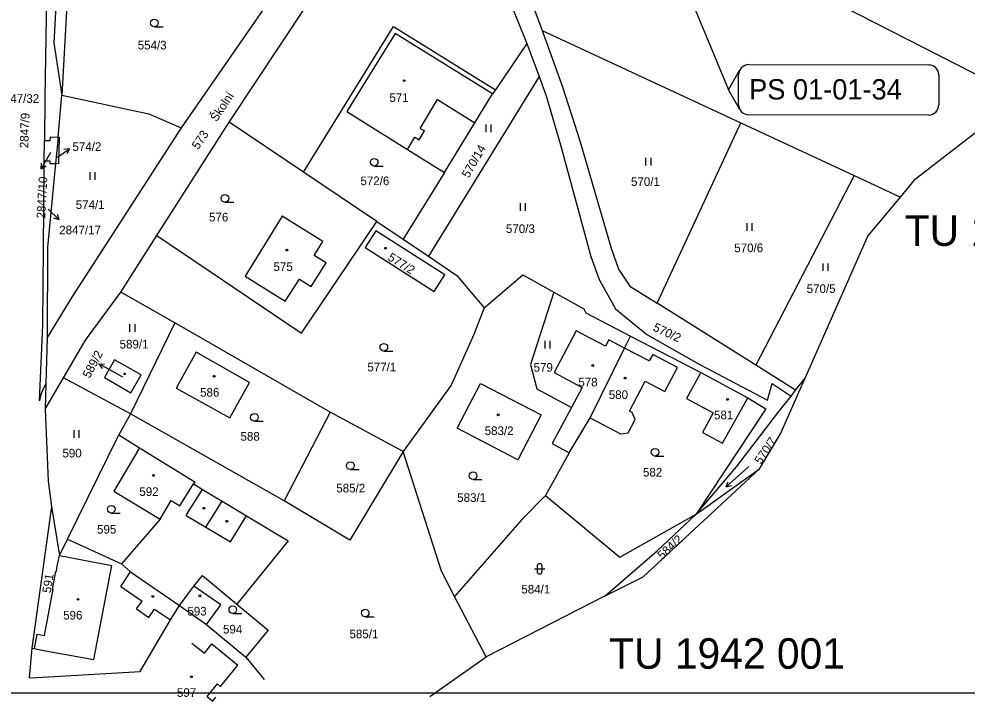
# Model space of a CAD drawing. Extents: x -558358 to -557517, y -1073786 to -1073189.
# Drawn here: x -558184.5 to -557998, y -1073785.7 to -1073651.5 of the extents above; entities that cross this region are included whole.
import ezdxf

# ---------------------------------------------------------------- set-up
doc = ezdxf.new("R2010")
doc.units = 0
for name, color, linetype in [('Hranice parcel', 7, 'Continuous'), ('Parcelní čísla', 7, 'Continuous'), ('Pop  PČ popisy', 7, 'Continuous'), ('Vnitřní kresba', 7, 'Continuous'), ('Vrstva 1', 7, 'Continuous'), ('Vrstva 2', 7, 'Continuous'), ('Vrstva 28', 7, 'Continuous'), ('Značky budov', 7, 'Continuous'), ('Značky kultur', 7, 'Continuous')]:
    doc.layers.add(name, color=color, linetype=linetype)

msp = doc.modelspace()

# ---------------------------------------------------------------- linework, layer by layer
at = {"layer": 'Hranice parcel'}
for p, q in [((-558126.57, -1073635.37), (-558152.59, -1073672.96)), ((-558047.53, -1073636.2), (-557987.38, -1073666.93)), ((-558083.83, -1073647.78), (-558081.75, -1073653.27)), ((-558081.75, -1073653.27), (-558081.56, -1073653.8)), ((-558081.56, -1073653.8), (-558042.48, -1073671.96)), ((-558084.61, -1073656.37), (-558090.78, -1073665.45)), ((-558084.61, -1073656.37), (-558082.19, -1073662.86)), ((-558082.19, -1073662.86), (-558103.95, -1073698.19)), ((-558082.19, -1073662.86), (-558080.79, -1073666.61)), ((-558090.78, -1073665.45), (-558091.34, -1073666.27)), ((-558176.83, -1073674.75), (-558176.05, -1073666.5)), ((-558008.13, -1073682.96), (-557987.38, -1073666.93)), ((-558157.39, -1073694.14), (-558143.16, -1073671.79)), ((-558128.54, -1073681.64), (-558143.16, -1073671.79)), ((-558058.98, -1073707.44), (-558042.48, -1073671.96)), ((-558042.48, -1073671.96), (-558020.18, -1073682.32)), ((-558178.3, -1073674.68), (-558176.83, -1073674.75)), ((-558176.83, -1073674.75), (-558177.33, -1073679.98)), ((-558176.83, -1073674.75), (-558176.6, -1073674.76)), ((-558176.6, -1073674.76), (-558176.71, -1073680)), ((-558179.54, -1073679.43), (-558179.49, -1073675.4)), ((-558178.45, -1073679.93), (-558177.33, -1073679.98)), ((-558176.71, -1073680), (-558177.33, -1073679.98)), ((-558114.13, -1073691.34), (-558128.54, -1073681.64)), ((-558100.81, -1073681.69), (-558108.93, -1073694.83)), ((-558020.18, -1073682.32), (-558039.55, -1073719.63)), ((-558020.18, -1073682.32), (-558011.11, -1073686.54)), ((-558011.11, -1073686.54), (-558008.13, -1073682.96)), ((-558017.53, -1073694.23), (-558011.11, -1073686.54)), ((-558114.13, -1073691.34), (-558108.93, -1073694.83)), ((-558164.46, -1073705.23), (-558157.39, -1073694.14)), ((-558108.93, -1073694.83), (-558103.95, -1073698.19)), ((-558029.85, -1073722.15), (-558017.53, -1073694.23)), ((-558153.86, -1073711.3), (-558164.46, -1073705.23)), ((-558079.26, -1073705.23), (-558083.89, -1073719.49)), ((-558039.55, -1073719.63), (-558058.98, -1073707.44)), ((-558153.86, -1073711.3), (-558162.58, -1073729.18)), ((-558123.29, -1073728.86), (-558153.86, -1073711.3)), ((-558178.98, -1073714.16), (-558179.23, -1073723.31)), ((-558065.38, -1073716.24), (-558064.19, -1073713.89)), ((-558064.19, -1073713.89), (-558050.38, -1073721.04)), ((-558072.16, -1073729.98), (-558065.38, -1073716.24)), ((-558083.89, -1073719.49), (-558082.62, -1073724.25)), ((-558031.72, -1073724.54), (-558039.55, -1073719.63)), ((-558050.38, -1073721.04), (-558041.12, -1073726.03)), ((-558179.37, -1073728.25), (-558175.74, -1073722.09)), ((-558179.23, -1073723.31), (-558179.37, -1073728.25)), ((-558162.58, -1073729.18), (-558175.74, -1073722.09)), ((-558031.72, -1073724.54), (-558029.85, -1073722.15)), ((-558082.62, -1073724.25), (-558075.83, -1073727.93)), ((-558032.62, -1073725.69), (-558031.72, -1073724.54)), ((-558162.58, -1073729.18), (-558164.87, -1073733.32)), ((-558132.34, -1073746.32), (-558162.58, -1073729.18)), ((-558123.29, -1073728.86), (-558132.34, -1073746.32)), ((-558108.92, -1073736.57), (-558123.29, -1073728.86)), ((-558076.28, -1073736.83), (-558072.16, -1073729.98)), ((-558174.95, -1073753.84), (-558164.87, -1073733.32)), ((-558164.87, -1073733.32), (-558160.79, -1073735.84)), ((-558076.28, -1073736.83), (-558080.95, -1073745.27)), ((-558061.7, -1073761.21), (-558038.85, -1073740)), ((-558051.32, -1073748.93), (-558043.37, -1073739.61)), ((-558051.32, -1073748.93), (-558038.85, -1073740)), ((-558080.95, -1073745.27), (-558085.52, -1073749.88)), ((-558178.08, -1073747.39), (-558181.97, -1073775.25)), ((-558178.08, -1073747.39), (-558176.52, -1073757.07)), ((-558058.99, -1073756.15), (-558051.32, -1073748.93)), ((-558085.52, -1073749.88), (-558098.82, -1073765.08)), ((-558176.52, -1073757.07), (-558174.95, -1073753.84)), ((-558174.95, -1073753.84), (-558164.36, -1073758.7)), ((-558069.16, -1073765.01), (-558058.99, -1073756.15)), ((-558069.16, -1073765.01), (-558061.7, -1073761.21)), ((-558152.96, -1073766.88), (-558150.14, -1073763.05)), ((-558092.62, -1073776.97), (-558098.82, -1073765.08)), ((-558069.16, -1073765.01), (-558092.62, -1073776.97)), ((-558152.96, -1073766.88), (-558147.64, -1073770.59)), ((-558147.64, -1073770.59), (-558147.54, -1073770.67)), ((-558147.54, -1073770.67), (-558139.85, -1073777.06)), ((-558181.97, -1073775.25), (-558182.51, -1073781.13)), ((-558139.85, -1073777.06), (-558136.25, -1073781.43)), ((-558103.7, -1073784.79), (-558092.62, -1073776.97)), ((-558182.51, -1073781.13), (-558181.01, -1073781.05))]:
    msp.add_line(p, q, dxfattribs=at)
for points in [[(-558086.19, -1073392.25), (-558100.56, -1073410.01), (-558117.51, -1073431.08), (-558131.78, -1073449.27), (-558138.48, -1073457.68), (-558143.38, -1073464.02), (-558146.99, -1073468.89), (-558150.46, -1073473.83), (-558152.02, -1073476.41), (-558154.26, -1073480.97), (-558156.46, -1073486.6), (-558158.91, -1073494.31), (-558160.3, -1073500.48), (-558162.16, -1073510.4), (-558165.76, -1073536.46), (-558169.94, -1073565.43), (-558173.74, -1073591.61), (-558177.66, -1073620.33), (-558178.51, -1073631.87), (-558179.02, -1073643), (-558179.24, -1073655.12), (-558179.45, -1073666.94), (-558179.49, -1073675.4)], [(-558175.82, -1073622.18), (-558177.63, -1073656.22), (-558176.05, -1073666.5)], [(-558175.82, -1073622.18), (-558174.18, -1073632.38), (-558176.05, -1073666.5)], [(-558143.16, -1073671.79), (-558122.68, -1073640.91), (-558116.74, -1073631.82), (-558110.18, -1073623.69)], [(-558110.18, -1073623.69), (-558095.16, -1073631.27), (-558088.2, -1073647.35), (-558084.61, -1073656.37)], [(-558128.54, -1073681.64), (-558110.84, -1073652.98), (-558090.78, -1073665.45)], [(-558091.34, -1073666.27), (-558110.52, -1073654.36), (-558120.01, -1073669.73), (-558108.1, -1073677.21), (-558100.81, -1073681.69)], [(-558081.56, -1073653.8), (-558077.6, -1073664.88), (-558074.09, -1073675.7), (-558068.03, -1073696.59), (-558066.56, -1073700.76), (-558064.34, -1073704.08), (-558058.98, -1073707.44)], [(-558176.05, -1073666.5), (-558158.95, -1073670.2), (-558152.59, -1073672.96)], [(-558100.81, -1073681.69), (-558094.8, -1073671.95), (-558091.34, -1073666.27)], [(-558080.79, -1073666.61), (-558077.98, -1073676.29), (-558072.03, -1073698.27), (-558070.37, -1073702.74), (-558067.15, -1073708.5), (-558060.97, -1073713.55), (-558050.8, -1073719.38), (-558037.27, -1073726.47), (-558036.33, -1073723.21), (-558032.62, -1073725.69)], [(-558152.59, -1073672.96), (-558174.12, -1073706.25), (-558178.98, -1073714.16)], [(-558179.49, -1073675.4), (-558178.35, -1073675.4), (-558178.3, -1073674.68)], [(-558180.47, -1073726.64), (-558179.79, -1073711.73), (-558179.61, -1073688.81), (-558179.54, -1073679.43)], [(-558179.54, -1073679.43), (-558178.44, -1073679.44), (-558178.45, -1073679.93)], [(-558177.33, -1073679.98), (-558178.88, -1073696.38), (-558178.98, -1073714.16)], [(-558157.39, -1073694.14), (-558128.92, -1073713.32), (-558114.13, -1073691.34)], [(-558124.75, -1073695.3), (-558132.74, -1073690.28), (-558139.98, -1073702.13), (-558132.13, -1073707.05), (-558129.35, -1073702.69), (-558127, -1073704.15), (-558124.1, -1073699.49), (-558126.45, -1073698.03), (-558124.75, -1073695.3)], [(-558114.32, -1073693.16), (-558116.42, -1073696.46), (-558102.81, -1073705.11), (-558100.72, -1073701.82), (-558114.32, -1073693.16)], [(-558103.95, -1073698.19), (-558098.36, -1073701.95), (-558092.97, -1073708.36)], [(-558092.97, -1073708.36), (-558085.4, -1073701.82), (-558079.26, -1073705.23)], [(-558175.74, -1073722.09), (-558171.39, -1073714.72), (-558164.46, -1073705.23)], [(-558079.26, -1073705.23), (-558073.37, -1073708.51), (-558073.01, -1073709.33), (-558064.19, -1073713.89)], [(-558092.97, -1073708.36), (-558095.02, -1073713.61), (-558099.46, -1073723.54), (-558108.92, -1073736.57)], [(-558065.38, -1073716.24), (-558068.48, -1073714.62), (-558069.13, -1073715.86), (-558074.89, -1073712.87), (-558079.25, -1073721.04), (-558073.73, -1073723.99), (-558075.83, -1073727.93)], [(-558072.16, -1073729.98), (-558066.15, -1073733.15), (-558064.66, -1073732.92), (-558063.26, -1073730.33), (-558063.88, -1073728.9), (-558064.4, -1073728.63), (-558061.31, -1073722.78), (-558057.44, -1073724.76), (-558054.98, -1073720.06), (-558059.84, -1073717.49), (-558060.51, -1073718.77), (-558065.38, -1073716.24)], [(-558139.17, -1073722.99), (-558149.67, -1073717.07), (-558153.56, -1073724.14), (-558143.05, -1073729.97), (-558139.17, -1073722.99)], [(-558160.49, -1073721.53), (-558165.71, -1073718.57), (-558167.69, -1073722.06), (-558162.47, -1073725.03), (-558160.49, -1073721.53)], [(-558050.38, -1073721.04), (-558053.17, -1073726.18), (-558047.96, -1073729.01), (-558050.05, -1073732.86), (-558046.14, -1073734.98), (-558041.12, -1073726.03)], [(-558179.23, -1073723.31), (-558179.97, -1073724.66), (-558180.29, -1073725.65), (-558180.47, -1073726.64)], [(-558081.79, -1073729.39), (-558086.39, -1073738.22), (-558098.32, -1073732.01), (-558093.7, -1073723.21), (-558081.79, -1073729.39)], [(-558031.69, -1073726.31), (-558031.08, -1073724.94), (-558029.85, -1073722.15)], [(-558041.12, -1073726.03), (-558037.61, -1073728.19), (-558051.32, -1073748.93)], [(-558043.37, -1073739.61), (-558035.2, -1073729), (-558032.62, -1073725.69)], [(-558038.85, -1073740), (-558034.7, -1073733.14), (-558031.69, -1073726.31)], [(-558179.37, -1073728.25), (-558178.74, -1073742.4), (-558178.08, -1073747.39)], [(-558075.83, -1073727.93), (-558079.61, -1073735.04), (-558076.28, -1073736.83)], [(-558160.79, -1073735.84), (-558165.86, -1073744.39), (-558156.72, -1073749.9), (-558164.36, -1073758.7)], [(-558160.79, -1073735.84), (-558149.94, -1073742.55), (-558150.18, -1073742.93), (-558148.38, -1073744.09), (-558144.55, -1073746.39), (-558139.78, -1073749.25), (-558131.58, -1073754.18), (-558141.63, -1073766.63)], [(-558108.92, -1073736.57), (-558119.39, -1073754.05), (-558132.34, -1073746.32)], [(-558098.82, -1073765.08), (-558101.41, -1073760.13), (-558108.92, -1073736.57)], [(-558080.95, -1073745.27), (-558066.32, -1073757.38), (-558051.32, -1073748.93)], [(-558181.97, -1073775.25), (-558181.48, -1073775.34), (-558180.95, -1073772.5), (-558179.48, -1073772.78), (-558177.77, -1073763.68), (-558177.92, -1073763.66), (-558177.27, -1073760.18), (-558177.12, -1073760.21), (-558177.05, -1073759.47), (-558176.52, -1073757.07)], [(-558164.36, -1073758.7), (-558162.58, -1073760.28), (-558152.96, -1073766.88)], [(-558150.14, -1073763.05), (-558148.43, -1073760.98), (-558141.63, -1073766.63)], [(-558147.64, -1073770.59), (-558144.77, -1073766.75), (-558150.14, -1073763.05)], [(-558181.01, -1073781.05), (-558160.65, -1073779.83), (-558154.69, -1073769.71), (-558152.96, -1073766.88)], [(-558141.63, -1073766.63), (-558135.48, -1073771.74), (-558139.85, -1073777.06)]]:
    msp.add_lwpolyline(points, dxfattribs=at)
at = {"layer": 'Pop  PČ popisy'}
for p, q in [((-558177.05, -1073678.78), (-558174.59, -1073677.06)), ((-558174.59, -1073677.06), (-558175.7, -1073677.22)), ((-558174.59, -1073677.06), (-558175.12, -1073678.04)), ((-558178.66, -1073678.4), (-558180.11, -1073681.02)), ((-558178.32, -1073677.78), (-558178.66, -1073678.4)), ((-558180.11, -1073681.02), (-558180.07, -1073679.91)), ((-558180.11, -1073681.02), (-558179.19, -1073680.39)), ((-558178.75, -1073688.95), (-558176.59, -1073691.03)), ((-558176.59, -1073691.03), (-558176.96, -1073689.98)), ((-558176.59, -1073691.03), (-558177.66, -1073690.7)), ((-558166.16, -1073720.8), (-558168.79, -1073719.34)), ((-558168.79, -1073719.34), (-558167.67, -1073719.39)), ((-558168.79, -1073719.34), (-558168.15, -1073720.27)), ((-558164.05, -1073721.99), (-558166.16, -1073720.8))]:
    msp.add_line(p, q, dxfattribs=at)
at = {"layer": 'Vnitřní kresba'}
for p, q in [((-558105.6, -1073673.04), (-558102.19, -1073667.36)), ((-558102.19, -1073667.36), (-558094.8, -1073671.95)), ((-558105.6, -1073673.04), (-558104.74, -1073673.55)), ((-558108.1, -1073677.21), (-558106.65, -1073674.8)), ((-558106.65, -1073674.8), (-558105.79, -1073675.32)), ((-558105.79, -1073675.32), (-558104.74, -1073673.55)), ((-558152.86, -1073747.27), (-558150.18, -1073742.93)), ((-558151.46, -1073748.94), (-558148.38, -1073744.09)), ((-558156.72, -1073749.9), (-558154.56, -1073746.22)), ((-558154.56, -1073746.22), (-558152.86, -1073747.27)), ((-558147.74, -1073751.5), (-558144.55, -1073746.39)), ((-558151.61, -1073749.2), (-558151.46, -1073748.94)), ((-558151.61, -1073749.2), (-558147.74, -1073751.5)), ((-558142.92, -1073754.36), (-558139.78, -1073749.25)), ((-558147.74, -1073751.5), (-558142.92, -1073754.36)), ((-558176.52, -1073757.07), (-558166.27, -1073759.01)), ((-558169.76, -1073777.52), (-558166.27, -1073759.01)), ((-558164.5, -1073763.14), (-558162.58, -1073760.28)), ((-558164.5, -1073763.14), (-558160.25, -1073766.01)), ((-558161.38, -1073767.55), (-558160.25, -1073766.01)), ((-558161.38, -1073767.55), (-558158.98, -1073769.26)), ((-558158.98, -1073769.26), (-558157.87, -1073767.62)), ((-558157.87, -1073767.62), (-558154.69, -1073769.71)), ((-558181.48, -1073775.34), (-558180, -1073775.65)), ((-558180, -1073775.65), (-558169.76, -1073777.52)), ((-558150.48, -1073774.29), (-558148.03, -1073776.28)), ((-558148.03, -1073776.28), (-558146.55, -1073774.45)), ((-558146.55, -1073774.45), (-558141.43, -1073778.61)), ((-558144.83, -1073782.8), (-558141.43, -1073778.61)), ((-558147.47, -1073784.78), (-558145.45, -1073782.3)), ((-558145.45, -1073782.3), (-558144.83, -1073782.8)), ((-558147.47, -1073784.78), (-558146.38, -1073785.67)), ((-558146.38, -1073785.67), (-558145.78, -1073784.93))]:
    msp.add_line(p, q, dxfattribs=at)
at = {"layer": 'Vrstva 1'}
msp.add_line((-557516.53, -1073784.09), (-558357.53, -1073784.09), dxfattribs=at)
at = {"layer": 'Vrstva 28'}
for p, q in [((-558150.16, -1073413.05), (-558044.9, -1073665.43)), ((-558044.9, -1073665.43), (-558042.67, -1073661.51)), ((-558044.9, -1073665.43), (-558042.67, -1073661.51)), ((-558040.96, -1073660.51), (-558005.53, -1073660.57)), ((-558040.96, -1073660.51), (-558005.53, -1073660.57)), ((-558042.94, -1073668.38), (-558042.93, -1073662.48)), ((-558042.94, -1073668.38), (-558042.93, -1073662.48)), ((-558003.56, -1073662.54), (-558003.57, -1073668.45)), ((-558003.56, -1073662.54), (-558003.57, -1073668.45)), ((-558042.68, -1073669.35), (-558044.9, -1073665.43)), ((-558042.68, -1073669.35), (-558044.9, -1073665.43)), ((-558005.54, -1073670.41), (-558040.97, -1073670.36)), ((-558005.54, -1073670.41), (-558040.97, -1073670.36))]:
    msp.add_line(p, q, dxfattribs=at)
for centre, start, end in [((-558040.96, -1073662.48), 89.9095, 179.9095), ((-558040.96, -1073662.48), 89.9095, 179.9095), ((-558005.53, -1073662.54), 359.9095, 89.9095), ((-558005.53, -1073662.54), 359.9095, 89.9095), ((-558040.97, -1073668.39), 179.9095, 269.9095), ((-558040.97, -1073668.39), 179.9095, 269.9095), ((-558005.54, -1073668.44), 269.9095, 359.9095), ((-558005.54, -1073668.44), 269.9095, 359.9095)]:
    msp.add_arc(centre, 1.97, start, end, dxfattribs=at)
at = {"layer": 'Značky budov'}
for centre in [(-558108.71, -1073663.65), (-558131.8, -1073696.98), (-558112.42, -1073696.62), (-558071.63, -1073719.68), (-558163.71, -1073721.34), (-558146.11, -1073721.79), (-558065.25, -1073722.15), (-558045.1, -1073726.35), (-558090.22, -1073729.39), (-558158.06, -1073741.3), (-558148.12, -1073747.76), (-558143.62, -1073750.31), (-558172.89, -1073765.67), (-558158.17, -1073765.09), (-558148.92, -1073764.99), (-558150.58, -1073780.89)]:
    msp.add_circle(centre, 0.175, dxfattribs=at)
at = {"layer": 'Značky kultur'}
for p, q in [((-558157.86, -1073653.06), (-558156.11, -1073653.06)), ((-558092.63, -1073673.76), (-558092.63, -1073672.26)), ((-558091.63, -1073673.76), (-558091.63, -1073672.26)), ((-558061.16, -1073680.32), (-558061.16, -1073678.82)), ((-558060.16, -1073680.32), (-558060.16, -1073678.82)), ((-558114.63, -1073680.46), (-558112.88, -1073680.46)), ((-558170.5, -1073683.13), (-558170.5, -1073681.63)), ((-558169.5, -1073683.13), (-558169.5, -1073681.63)), ((-558144, -1073687.55), (-558142.25, -1073687.55)), ((-558085.83, -1073689.23), (-558085.83, -1073687.73)), ((-558084.83, -1073689.23), (-558084.83, -1073687.73)), ((-558041.24, -1073693.17), (-558041.24, -1073691.67)), ((-558040.24, -1073693.17), (-558040.24, -1073691.67)), ((-558026.3, -1073701.09), (-558026.3, -1073699.59)), ((-558025.3, -1073701.09), (-558025.3, -1073699.59)), ((-558162.67, -1073713.05), (-558162.67, -1073711.55)), ((-558161.67, -1073713.05), (-558161.67, -1073711.55)), ((-558080.99, -1073716.31), (-558080.99, -1073714.81)), ((-558079.99, -1073716.31), (-558079.99, -1073714.81)), ((-558112.73, -1073716.84), (-558110.98, -1073716.84)), ((-558138.2, -1073730.62), (-558136.45, -1073730.62)), ((-558173.68, -1073733.89), (-558173.68, -1073732.39)), ((-558172.68, -1073733.89), (-558172.68, -1073732.39)), ((-558059.37, -1073737.48), (-558057.62, -1073737.48)), ((-558119.32, -1073740.13), (-558117.57, -1073740.13)), ((-558040.91, -1073739.54), (-558045.37, -1073743.55)), ((-558095.17, -1073742.09), (-558093.42, -1073742.09)), ((-558045.37, -1073743.55), (-558044.98, -1073742.53)), ((-558045.37, -1073743.55), (-558044.31, -1073743.27)), ((-558166.36, -1073748.71), (-558164.61, -1073748.71)), ((-558083.08, -1073759.67), (-558081.08, -1073759.67)), ((-558082.58, -1073759.17), (-558082.58, -1073760.17)), ((-558081.58, -1073760.17), (-558081.58, -1073759.17)), ((-558142.44, -1073768.45), (-558140.69, -1073768.45)), ((-558116.4, -1073769.12), (-558114.65, -1073769.12))]:
    msp.add_line(p, q, dxfattribs=at)
for centre in [(-558157.86, -1073652.31), (-558114.63, -1073679.71), (-558144, -1073686.8), (-558112.73, -1073716.09), (-558138.2, -1073729.87), (-558059.37, -1073736.73), (-558119.32, -1073739.38), (-558095.17, -1073741.34), (-558166.36, -1073747.96), (-558142.44, -1073767.7), (-558116.4, -1073768.37)]:
    msp.add_circle(centre, 0.75, dxfattribs=at)
for centre, start, end in [((-558082.08, -1073759.17), 0, 180), ((-558082.08, -1073760.17), 180, 359.9879)]:
    msp.add_arc(centre, 0.5, start, end, dxfattribs=at)

# ---------------------------------------------------------------- texts
at = {"layer": 'Parcelní čísla'}
for s, p in [('554/3', (-558161.15, -1073657.52)), ('2847/32', (-558188.75, -1073668.02)), ('571', (-558111.64, -1073667.83)), ('574/2', (-558173.99, -1073677.47)), ('572/6', (-558117.34, -1073684.21)), ('570/1', (-558064.11, -1073684.36)), ('574/1', (-558173.35, -1073688.89)), ('576', (-558147.12, -1073691.34)), ('570/3', (-558088.71, -1073693.62)), ('2847/17', (-558176.59, -1073693.88)), ('570/6', (-558043.8, -1073697.39)), ('575', (-558134.43, -1073701.08)), ('570/5', (-558029.55, -1073705.42)), ('589/1', (-558164.71, -1073716.33)), ('577/1', (-558115.97, -1073720.83)), ('579', (-558083.27, -1073720.9)), ('578', (-558074.47, -1073723.79)), ('586', (-558148.88, -1073725.81)), ('580', (-558068.48, -1073726.26)), ('581', (-558047.78, -1073730.27)), ('588', (-558140.93, -1073734.47)), ('583/2', (-558092.9, -1073733.36)), ('590', (-558175.96, -1073737.76)), ('582', (-558061.75, -1073741.52)), ('592', (-558160.83, -1073745.33)), ('585/2', (-558122.09, -1073744.64)), ('583/1', (-558098.3, -1073746.51)), ('595', (-558169.15, -1073752.74)), ('584/1', (-558085.68, -1073764.52)), ('596', (-558175.82, -1073769.64)), ('593', (-558151.38, -1073768.85)), ('594', (-558144.37, -1073772.39)), ('585/1', (-558119.49, -1073773.32)), ('597', (-558153.44, -1073784.85))]:
    msp.add_text(s, height=1.7, dxfattribs=at).set_placement(p)
for s, rotation, p in [('2847/9', 88, (-558182.68, -1073676.97)), ('573', 56, (-558149.24, -1073677.32)), ('570/14', 60, (-558096.05, -1073682.93)), ('2847/10', 87, (-558179.35, -1073690.79)), ('577/2', 328, (-558112.11, -1073698.84)), ('570/2', 335, (-558059.92, -1073712.75)), ('589/2', 62, (-558170.6, -1073722.33)), ('570/7', 56, (-558038.56, -1073739.25)), ('584/2', 43, (-558057.95, -1073757.95)), ('591', 81, (-558178.26, -1073764.52))]:
    msp.add_text(s, height=1.7, rotation=rotation, dxfattribs=at).set_placement(p)
at = {"layer": 'Pop  PČ popisy'}
msp.add_text('Školní', height=1.7, rotation=56, dxfattribs=at).set_placement((-558145.62, -1073671.85))
at = {"layer": 'Vrstva 2'}
for s, p in [('TU 1942 002', (-558010.26, -1073696.15)), ('TU 1942 001', (-558068.41, -1073779.32))]:
    msp.add_text(s, height=6, dxfattribs=at).set_placement(p)
at = {"layer": 'Vrstva 28'}
msp.add_text('PS 01-01-34', height=4, dxfattribs=at).set_placement((-558040.87, -1073667.36))

doc.saveas('drawing.dxf')
